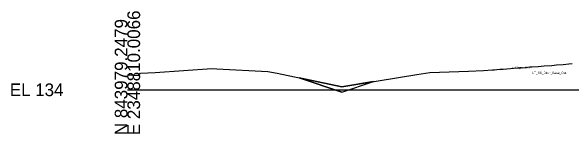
# Model space of a CAD drawing. Extents: x -26 to 2349090, y -10 to 844481.
# Drawn here: x 974.3 to 1098.3, y 16490.3 to 16517.3 of the extents above; entities that cross this region are included whole.
import ezdxf

# ---------------------------------------------------------------- set-up
doc = ezdxf.new("R2010")
doc.units = 0
for name, color, linetype in [('Exist Cross Section Cell', 7, 'Continuous'), ('Exist XS Ground Line', 7, 'Continuous'), ('Prop CMT Ditch DDE', 7, 'Continuous'), ('Prop Road Sect_ Recs - UUC (Outline)', 7, 'Continuous'), ('Scratch_Level_0', 7, 'Continuous')]:
    doc.layers.add(name, color=color, linetype=linetype)

msp = doc.modelspace()

# ---------------------------------------------------------------- linework, layer by layer
at = {"layer": 'Exist Cross Section Cell'}
msp.add_line((1000, 16500), (1150, 16500), dxfattribs=at)
at = {"layer": 'Exist XS Ground Line'}
msp.add_lwpolyline([(1000, 16503.3), (1002.44, 16503.15), (1002.86, 16503.65), (1006.1, 16503.83), (1018.68, 16504.68), (1019.74, 16504.64), (1031.02, 16504.04), (1033.08, 16503.65), (1047.41, 16500.68), (1055.47, 16502.01), (1064, 16503.36), (1066.87, 16503.8), (1075.44, 16504.13), (1078.75, 16504.27), (1080.72, 16504.39), (1081.16, 16504.42), (1081.68, 16504.47), (1082.32, 16504.54), (1083.09, 16504.58), (1083.88, 16504.63), (1085.47, 16504.75), (1086.57, 16504.84), (1086.97, 16504.87), (1087.91, 16504.95), (1088.96, 16505.03), (1089.41, 16505.07), (1090.83, 16505.17), (1092.18, 16505.27), (1093.81, 16505.39), (1094.89, 16505.48), (1096.37, 16505.61), (1097.62, 16505.72), (1098.3, 16505.78)], dxfattribs=at)
at = {"layer": 'Prop CMT Ditch DDE'}
for q in [(1038.01, 16502.63), (1054.44, 16501.84)]:
    msp.add_line((1047.41, 16499.5), q, dxfattribs=at)
at = {"layer": 'Prop Road Sect_ Recs - UUC (Outline)'}
msp.add_lwpolyline([(1038.01, 16502.63), (1047.41, 16499.5), (1054.44, 16501.84), (1047.41, 16500.68)], close=True, dxfattribs=at)

# ---------------------------------------------------------------- texts
at = {"layer": 'Exist Cross Section Cell'}
for s, p in [('E 2348810.0066', (1002.8, 16490)), ('N 843979.2479', (1000, 16490))]:
    msp.add_text(s, height=2.8, rotation=90, dxfattribs=at).set_placement(p)
msp.add_text('EL 134', height=2.8, dxfattribs=at).set_placement((974, 16498.6))
at = {"layer": 'Scratch_Level_0'}
for s, p in [('LT_Slope_Cut', (1084.5, 16504.63)), ('LT_SS_Ditch_Base_Out', (1089.52, 16503.48))]:
    msp.add_text(s, height=0.5, dxfattribs=at).set_placement(p)

doc.saveas('drawing.dxf')
